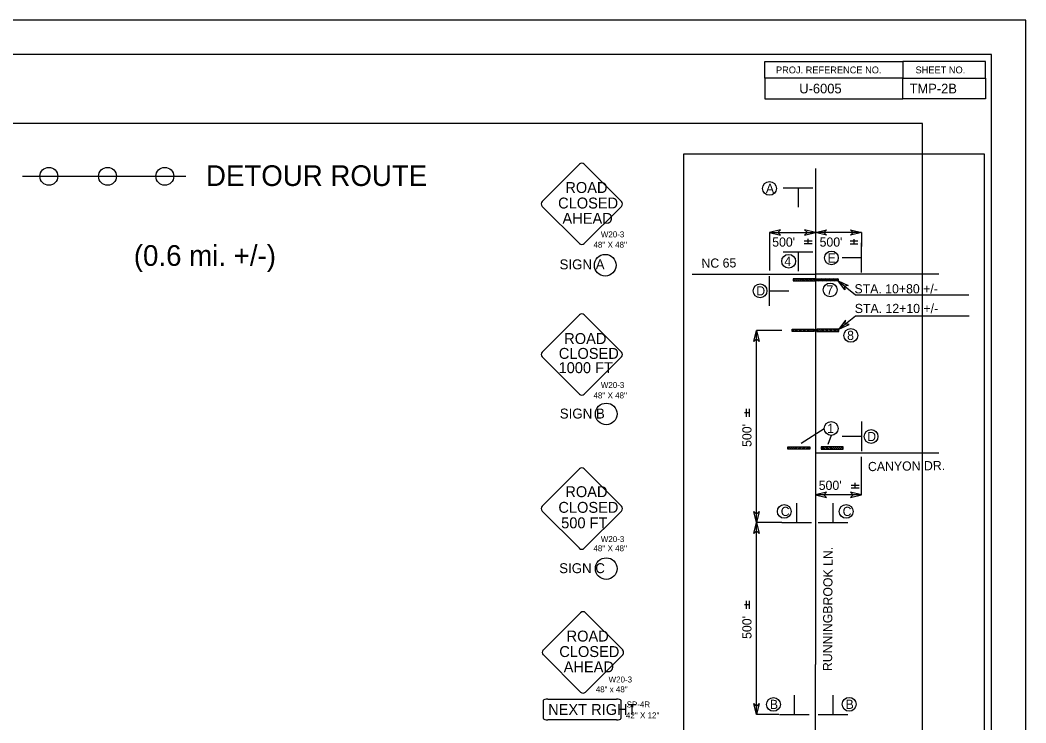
# Model space of a CAD drawing. Extents: x 1615234 to 1620694, y 898143 to 902846.
# Drawn here: x 1618110 to 1620298, y 901317 to 902846 of the extents above; entities that cross this region are included whole.
import ezdxf

# ---------------------------------------------------------------- set-up
doc = ezdxf.new("R2010")
doc.units = 0
for name, color, linetype in [('DEV BORDER CELL', 7, 'Continuous'), ('Old_Level_28', 7, 'Continuous'), ('Old_Level_8', 7, 'Continuous'), ('Scratch_Level_0', 7, 'Continuous'), ('Sheet Plot Border Outside CELL', 7, 'Continuous'), ('WZ INSETA CELL', 7, 'Continuous')]:
    doc.layers.add(name, color=color, linetype=linetype)

msp = doc.modelspace()

# ---------------------------------------------------------------- linework, layer by layer
at = {"layer": 'DEV BORDER CELL'}
msp.add_line((1620030, 902719.8), (1620210, 902719.8), dxfattribs=at)
for points in [[(1620223.1, 902771.2), (1615723.1, 902771.2), (1615723.1, 899621.2), (1620223.1, 899621.2)], [(1619730, 902755.8), (1620030, 902755.8), (1620030, 902719.8), (1619730, 902719.8)], [(1620030, 902719.8), (1620210, 902719.8), (1620210, 902755.8), (1620030, 902755.8)], [(1620030, 902719.8), (1619730, 902719.8), (1619730, 902674.8), (1620030, 902674.8)], [(1620030, 902719.8), (1620210, 902719.8), (1620210, 902674.8), (1620030, 902674.8)]]:
    msp.add_lwpolyline(points, close=True, dxfattribs=at)
at = {"layer": 'Old_Level_28'}
for p, q in [((1618114.5, 902506.3), (1618470.3, 902506.3)), ((1619418, 902441), (1619337.1, 902360)), ((1619418, 901777.9), (1619337.1, 901697)), ((1619258.2, 901368.9), (1619407, 901368.9))]:
    msp.add_line(p, q, dxfattribs=at)
for points in [[(1619245.4, 902451.7), (1619326.4, 902532.6)], [(1619337.1, 902532.6), (1619418, 902451.7)], [(1619326.4, 902360), (1619245.4, 902441)], [(1619245.4, 902123.9), (1619326.4, 902204.8)], [(1619337.1, 902204.8), (1619418, 902123.9)], [(1619326.4, 902032.3), (1619245.4, 902113.2)], [(1619418, 902113.2), (1619337.1, 902032.3)], [(1619245.4, 901788.6), (1619326.4, 901869.5)], [(1619337.1, 901869.5), (1619418, 901788.6)], [(1619326.4, 901697), (1619245.4, 901777.9)], [(1619248.1, 901475.7), (1619329.1, 901556.6)], [(1619339.7, 901556.6), (1619420.7, 901475.7)], [(1619329.1, 901384), (1619248.1, 901465)], [(1619420.7, 901465), (1619339.7, 901384)], [(1619248.3, 901326.2), (1619248.3, 901366.2)], [(1619416.8, 901366.2), (1619416.8, 901326.2)], [(1619407, 901323.5), (1619258.2, 901323.5)]]:
    msp.add_lwpolyline(points, dxfattribs=at)
for centre in [(1619382.7, 902312.8), (1619385, 901989.2), (1619385, 901652.6)]:
    msp.add_circle(centre, 23.6, dxfattribs=at)
for centre, start, end in [((1619331.7, 902527.3), 44.987, 135), ((1619250.8, 902446.3), 135, 225), ((1619412.7, 902446.3), 315, 45), ((1619331.7, 902365.4), 225, 315), ((1619331.7, 902199.5), 44.987, 135), ((1619250.8, 902118.6), 135, 225), ((1619412.7, 902118.6), 315, 45), ((1619331.7, 902037.6), 225, 315), ((1619331.7, 901864.2), 44.987, 135), ((1619250.8, 901783.2), 135, 225), ((1619412.7, 901783.2), 315, 45), ((1619331.7, 901702.3), 225, 315), ((1619334.4, 901551.3), 44.987, 135), ((1619253.4, 901470.3), 135, 225), ((1619415.3, 901470.3), 315, 45), ((1619334.4, 901389.4), 225, 315)]:
    msp.add_arc(centre, 7.56, start, end, dxfattribs=at)
for centre, major_axis, start_param, end_param in [((1619258.2, 901366.2), (-9.83, 0), 4.712162, 6.283185), ((1619407, 901366.2), (9.83, 0), 0, 1.570796), ((1619258.2, 901326.2), (-9.83, 0), 0, 1.570796), ((1619407, 901326.2), (-9.83, 0), 1.570796, 3.141593)]:
    msp.add_ellipse(centre, major_axis=major_axis, ratio=0.269231, start_param=start_param, end_param=end_param, dxfattribs=at)
at = {"layer": 'Old_Level_8'}
for centre in [(1618172.1, 902506.3), (1618299.8, 902506.3), (1618424.4, 902506.3)]:
    msp.add_circle(centre, 19.5, dxfattribs=at)
at = {"layer": 'Scratch_Level_0'}
msp.add_lwpolyline([(1620073.1, 902621.2), (1615873.1, 902621.2), (1615873.1, 899771.2), (1618509.6, 899771.2), (1618509.6, 900126), (1620073.1, 900126)], close=True, dxfattribs=at)
at = {"layer": 'Sheet Plot Border Outside CELL'}
msp.add_lwpolyline([(1615234.1, 899546.2), (1620298.1, 899546.2), (1620298.1, 902846.2), (1615234.1, 902846.2)], close=True, dxfattribs=at)
at = {"layer": 'WZ INSETA CELL'}
for p, q in [((1619840.4, 902523.5), (1619840.4, 902393.2)), ((1619769.9, 902481.4), (1619834.7, 902481.4)), ((1619802.6, 902481.4), (1619802.6, 902439.4)), ((1619764.3, 902390.1), (1619740.4, 902384.2)), ((1619758.3, 902384.2), (1619764.3, 902390.1)), ((1619840.4, 902384.2), (1619816.6, 902390.1)), ((1619816.6, 902390.1), (1619822.6, 902384.2)), ((1619840.4, 902393.2), (1619840.4, 902293.4)), ((1619840.4, 902384.2), (1619864.3, 902390.1)), ((1619864.3, 902390.1), (1619858.3, 902384.2)), ((1619916.6, 902390.1), (1619940.4, 902384.2)), ((1619922.6, 902384.2), (1619916.6, 902390.1)), ((1619740.4, 902384.2), (1619840.4, 902384.2)), ((1619740.4, 902384.2), (1619764.3, 902378.2)), ((1619740.4, 902384.2), (1619740.4, 902301.5)), ((1619764.3, 902378.2), (1619758.3, 902384.2)), ((1619832.8, 902365.5), (1619815.5, 902365.5)), ((1619816.6, 902378.2), (1619840.4, 902384.2)), ((1619822.6, 902384.2), (1619816.6, 902378.2)), ((1619824.1, 902365.5), (1619824.1, 902370.1)), ((1619824.1, 902360.9), (1619824.1, 902365.5)), ((1619940.4, 902384.2), (1619840.4, 902384.2)), ((1619864.3, 902378.2), (1619840.4, 902384.2)), ((1619858.3, 902384.2), (1619864.3, 902378.2)), ((1619932.7, 902365.1), (1619915.4, 902365.1)), ((1619940.4, 902384.2), (1619916.6, 902378.2)), ((1619916.6, 902378.2), (1619922.6, 902384.2)), ((1619924.1, 902365.1), (1619924.1, 902369.7)), ((1619924.1, 902360.5), (1619924.1, 902365.1)), ((1619940.4, 902384.2), (1619940.4, 902353.7)), ((1619769.9, 902342.1), (1619834.7, 902342.1)), ((1619802.6, 902342.1), (1619802.6, 902300.1)), ((1619832.8, 902359.5), (1619815.5, 902359.5)), ((1619932.7, 902359), (1619915.4, 902359)), ((1619940.4, 902296.7), (1619940.4, 902361.5)), ((1619940.4, 902329.3), (1619898.5, 902329.3)), ((1619572.2, 902293.4), (1619723.2, 902293.4)), ((1619723.2, 902293.4), (1619840.4, 902293.4)), ((1619740.4, 902224.3), (1619740.4, 902289.1)), ((1619791.4, 902283.4), (1619791.4, 902278.6)), ((1619796.2, 902278.6), (1619791.4, 902283.4)), ((1619791.4, 902278.6), (1619796.2, 902278.6)), ((1619795.7, 902283.4), (1619800.5, 902278.6)), ((1619800.1, 902283.4), (1619795.7, 902283.4)), ((1619804.8, 902278.6), (1619800.1, 902283.4)), ((1619800.5, 902278.6), (1619804.8, 902278.6)), ((1619804.4, 902283.4), (1619809.1, 902278.6)), ((1619808.7, 902283.4), (1619804.4, 902283.4)), ((1619813.4, 902278.6), (1619808.7, 902283.4)), ((1619809.1, 902278.6), (1619813.4, 902278.6)), ((1619813, 902283.4), (1619817.7, 902278.6)), ((1619817.3, 902283.4), (1619813, 902283.4)), ((1619822, 902278.6), (1619817.3, 902283.4)), ((1619817.7, 902278.6), (1619822, 902278.6)), ((1619821.6, 902283.4), (1619826.4, 902278.6)), ((1619825.9, 902283.4), (1619821.6, 902283.4)), ((1619830.7, 902278.6), (1619825.9, 902283.4)), ((1619826.4, 902278.6), (1619830.7, 902278.6)), ((1619830.2, 902283.4), (1619835, 902278.6)), ((1619834.5, 902283.4), (1619830.2, 902283.4)), ((1619839.3, 902278.6), (1619834.5, 902283.4)), ((1619835, 902278.6), (1619839.3, 902278.6)), ((1620108.7, 902293.4), (1619840.4, 902293.4)), ((1619840.4, 902293.4), (1619840.4, 902104.6)), ((1619840.4, 902293.4), (1619840.4, 902104.6)), ((1619841.4, 902278.6), (1619841.4, 902283.4)), ((1619841.4, 902283.4), (1619846.1, 902283.4)), ((1619846.1, 902283.4), (1619841.4, 902278.6)), ((1619845.7, 902278.6), (1619850.5, 902283.4)), ((1619850, 902278.6), (1619845.7, 902278.6)), ((1619854.8, 902283.4), (1619850, 902278.6)), ((1619850.5, 902283.4), (1619854.8, 902283.4)), ((1619854.4, 902278.6), (1619859.1, 902283.4)), ((1619858.7, 902278.6), (1619854.4, 902278.6)), ((1619863.4, 902283.4), (1619858.7, 902278.6)), ((1619859.1, 902283.4), (1619863.4, 902283.4)), ((1619863, 902278.6), (1619867.7, 902283.4)), ((1619867.3, 902278.6), (1619863, 902278.6)), ((1619872, 902283.4), (1619867.3, 902278.6)), ((1619867.7, 902283.4), (1619872, 902283.4)), ((1619871.6, 902278.6), (1619876.4, 902283.4)), ((1619875.9, 902278.6), (1619871.6, 902278.6)), ((1619880.7, 902283.4), (1619875.9, 902278.6)), ((1619876.4, 902283.4), (1619880.7, 902283.4)), ((1619880.2, 902278.6), (1619885, 902283.4)), ((1619884.5, 902278.6), (1619880.2, 902278.6)), ((1619889.3, 902283.4), (1619884.5, 902278.6)), ((1619885, 902283.4), (1619889.3, 902283.4)), ((1619889.3, 902278.7), (1619927, 902248.3)), ((1619904.1, 902259.1), (1619889.3, 902278.7)), ((1619889.3, 902278.7), (1619911.6, 902268.4)), ((1619740.4, 902256.9), (1619782.4, 902256.9)), ((1619911.6, 902268.4), (1619903.2, 902267.5)), ((1619903.2, 902267.5), (1619904.1, 902259.1)), ((1619927, 902248.3), (1620174.2, 902248.3)), ((1619891.1, 902173.4), (1619927.5, 902202.9)), ((1619905.8, 902193), (1619891.1, 902173.4)), ((1619904.9, 902184.6), (1619905.8, 902193)), ((1619927.5, 902202.9), (1620174.7, 902202.9)), ((1619705.9, 902147), (1619711.9, 902170.8)), ((1619766.7, 902170.8), (1619711.9, 902170.8)), ((1619711.9, 901753), (1619711.9, 902170.8)), ((1619711.9, 902170.8), (1619717.8, 902147)), ((1619789.5, 902168.6), (1619794.3, 902173.4)), ((1619793.8, 902168.6), (1619789.5, 902168.6)), ((1619798.6, 902173.4), (1619793.8, 902168.6)), ((1619794.3, 902173.4), (1619798.6, 902173.4)), ((1619798.1, 902168.6), (1619802.9, 902173.4)), ((1619802.4, 902168.6), (1619798.1, 902168.6)), ((1619807.2, 902173.4), (1619802.4, 902168.6)), ((1619802.9, 902173.4), (1619807.2, 902173.4)), ((1619806.8, 902168.6), (1619811.5, 902173.4)), ((1619811.1, 902168.6), (1619806.8, 902168.6)), ((1619815.8, 902173.4), (1619811.1, 902168.6)), ((1619811.5, 902173.4), (1619815.8, 902173.4)), ((1619815.4, 902168.6), (1619820.1, 902173.4)), ((1619819.7, 902168.6), (1619815.4, 902168.6)), ((1619824.4, 902173.4), (1619819.7, 902168.6)), ((1619820.1, 902173.4), (1619824.4, 902173.4)), ((1619824, 902168.6), (1619828.7, 902173.4)), ((1619828.3, 902168.6), (1619824, 902168.6)), ((1619833, 902173.4), (1619828.3, 902168.6)), ((1619828.7, 902173.4), (1619833, 902173.4)), ((1619832.6, 902168.6), (1619837.3, 902173.4)), ((1619837.3, 902168.6), (1619832.6, 902168.6)), ((1619837.3, 902173.4), (1619837.3, 902168.6)), ((1619847.5, 902173.4), (1619843.2, 902173.4)), ((1619843.2, 902173.4), (1619848, 902168.6)), ((1619852.3, 902168.6), (1619847.5, 902173.4)), ((1619848, 902168.6), (1619852.3, 902168.6)), ((1619856.1, 902173.4), (1619851.8, 902173.4)), ((1619851.8, 902173.4), (1619856.6, 902168.6)), ((1619860.9, 902168.6), (1619856.1, 902173.4)), ((1619856.6, 902168.6), (1619860.9, 902168.6)), ((1619864.8, 902173.4), (1619860.5, 902173.4)), ((1619860.5, 902173.4), (1619865.2, 902168.6)), ((1619869.5, 902168.6), (1619864.8, 902173.4)), ((1619865.2, 902168.6), (1619869.5, 902168.6)), ((1619873.4, 902173.4), (1619869.1, 902173.4)), ((1619869.1, 902173.4), (1619873.8, 902168.6)), ((1619878.1, 902168.6), (1619873.4, 902173.4)), ((1619873.8, 902168.6), (1619878.1, 902168.6)), ((1619882, 902173.4), (1619877.7, 902173.4)), ((1619877.7, 902173.4), (1619882.4, 902168.6)), ((1619886.7, 902168.6), (1619882, 902173.4)), ((1619882.4, 902168.6), (1619886.7, 902168.6)), ((1619891.1, 902173.4), (1619886.3, 902173.4)), ((1619886.3, 902173.4), (1619891.1, 902168.6)), ((1619891.1, 902173.4), (1619913.3, 902183.7)), ((1619891.1, 902168.6), (1619891.1, 902173.4)), ((1619913.3, 902183.7), (1619904.9, 902184.6)), ((1619711.9, 902153), (1619705.9, 902147)), ((1619717.8, 902147), (1619711.9, 902153)), ((1619840.4, 902104.6), (1619840.4, 902015.2)), ((1619840.4, 902015.2), (1619840.4, 901715)), ((1619690.5, 901991.5), (1619685.9, 901991.5)), ((1619690.5, 901982.9), (1619690.5, 902000.2)), ((1619695.1, 901991.5), (1619690.5, 901991.5)), ((1619696.5, 901982.9), (1619696.5, 902000.2)), ((1619940.4, 901972.9), (1619940.4, 901908.1)), ((1619809.2, 901925.5), (1619859.3, 901957.7)), ((1619874.3, 901942.7), (1619867.1, 901923.1)), ((1619940.4, 901940.3), (1619898.5, 901940.3)), ((1619780.2, 901912.7), (1619785, 901917.5)), ((1619784.5, 901912.7), (1619780.2, 901912.7)), ((1619789.3, 901917.5), (1619784.5, 901912.7)), ((1619785, 901917.5), (1619789.3, 901917.5)), ((1619788.8, 901912.7), (1619793.6, 901917.5)), ((1619793.1, 901912.7), (1619788.8, 901912.7)), ((1619797.9, 901917.5), (1619793.1, 901912.7)), ((1619793.6, 901917.5), (1619797.9, 901917.5)), ((1619797.5, 901912.7), (1619802.2, 901917.5)), ((1619801.8, 901912.7), (1619797.5, 901912.7)), ((1619806.6, 901917.5), (1619801.8, 901912.7)), ((1619802.2, 901917.5), (1619806.6, 901917.5)), ((1619806.2, 901912.7), (1619810.9, 901917.5)), ((1619810.5, 901912.7), (1619806.2, 901912.7)), ((1619815.2, 901917.5), (1619810.5, 901912.7)), ((1619810.9, 901917.5), (1619815.2, 901917.5)), ((1619814.8, 901912.7), (1619819.5, 901917.5)), ((1619819.1, 901912.7), (1619814.8, 901912.7)), ((1619823.8, 901917.5), (1619819.1, 901912.7)), ((1619819.5, 901917.5), (1619823.8, 901917.5)), ((1619823.4, 901912.7), (1619828.1, 901917.5)), ((1619828.1, 901912.7), (1619823.4, 901912.7)), ((1619828.1, 901917.5), (1619828.1, 901912.7)), ((1619856.7, 901917.4), (1619852.4, 901917.4)), ((1619852.4, 901917.4), (1619857.2, 901912.6)), ((1619861.5, 901912.6), (1619856.7, 901917.4)), ((1619857.2, 901912.6), (1619861.5, 901912.6)), ((1619865.3, 901917.4), (1619861, 901917.4)), ((1619861, 901917.4), (1619865.8, 901912.6)), ((1619870.1, 901912.6), (1619865.3, 901917.4)), ((1619865.8, 901912.6), (1619870.1, 901912.6)), ((1619874, 901917.4), (1619869.7, 901917.4)), ((1619869.7, 901917.4), (1619874.4, 901912.6)), ((1619878.8, 901912.6), (1619874, 901917.4)), ((1619874.4, 901912.6), (1619878.8, 901912.6)), ((1619882.7, 901917.4), (1619878.3, 901917.4)), ((1619878.3, 901917.4), (1619883.1, 901912.6)), ((1619887.4, 901912.6), (1619882.7, 901917.4)), ((1619883.1, 901912.6), (1619887.4, 901912.6)), ((1619891.3, 901917.4), (1619887, 901917.4)), ((1619887, 901917.4), (1619891.7, 901912.6)), ((1619896, 901912.6), (1619891.3, 901917.4)), ((1619891.7, 901912.6), (1619896, 901912.6)), ((1619900.3, 901917.4), (1619895.6, 901917.4)), ((1619895.6, 901917.4), (1619900.3, 901912.6)), ((1619900.3, 901912.6), (1619900.3, 901917.4)), ((1620108.7, 901903.8), (1619840.4, 901903.8)), ((1619940.4, 901813), (1619940.4, 901895.8)), ((1619926.5, 901834.4), (1619926.5, 901839)), ((1619864.3, 901819), (1619840.4, 901813)), ((1619858.3, 901813), (1619864.3, 901819)), ((1619940.4, 901813), (1619916.6, 901819)), ((1619916.6, 901819), (1619922.6, 901813)), ((1619917.8, 901834.4), (1619935.1, 901834.4)), ((1619917.8, 901828.4), (1619935.1, 901828.4)), ((1619926.5, 901829.8), (1619926.5, 901834.4)), ((1619799.4, 901753), (1619799.4, 901795)), ((1619940.4, 901813), (1619840.4, 901813)), ((1619840.4, 901813), (1619864.3, 901807.1)), ((1619864.3, 901807.1), (1619858.3, 901813)), ((1619878.8, 901753), (1619878.8, 901795)), ((1619916.6, 901807.1), (1619940.4, 901813)), ((1619922.6, 901813), (1619916.6, 901807.1)), ((1619711.9, 901753), (1619705.9, 901776.8)), ((1619705.9, 901776.8), (1619711.9, 901770.8)), ((1619717.8, 901776.8), (1619711.9, 901753)), ((1619711.9, 901770.8), (1619717.8, 901776.8)), ((1619705.9, 901729.2), (1619711.9, 901753)), ((1619711.9, 901335.1), (1619711.9, 901753)), ((1619711.9, 901753), (1619717.8, 901729.2)), ((1619766.7, 901753), (1619711.9, 901753)), ((1619766.7, 901753), (1619831.5, 901753)), ((1619846.2, 901753), (1619911, 901753)), ((1619711.9, 901735.1), (1619705.9, 901729.2)), ((1619717.8, 901729.2), (1619711.9, 901735.1)), ((1619840.4, 901715), (1619840.4, 901615)), ((1619840.4, 901615), (1619840.4, 901443.8)), ((1619690.5, 901565), (1619690.5, 901582.3)), ((1619696.5, 901565), (1619696.5, 901582.3)), ((1619690.5, 901573.6), (1619685.9, 901573.6)), ((1619695.1, 901573.6), (1619690.5, 901573.6)), ((1619840.4, 901274.7), (1619840.4, 901443.8)), ((1619711.9, 901335.1), (1619705.9, 901358.9)), ((1619705.9, 901358.9), (1619711.9, 901353)), ((1619717.8, 901358.9), (1619711.9, 901335.1)), ((1619711.9, 901353), (1619717.8, 901358.9)), ((1619794.3, 901335.1), (1619794.3, 901377.1)), ((1619878.8, 901335.1), (1619878.8, 901377.1)), ((1619760.3, 901335.1), (1619711.9, 901335.1)), ((1619761.6, 901335.1), (1619826.4, 901335.1)), ((1619846.2, 901335.1), (1619911, 901335.1))]:
    msp.add_line(p, q, dxfattribs=at)
for points in [[(1620207.6, 900319.6), (1619553.5, 900319.6), (1619553.5, 902555.4), (1620207.6, 902555.4)], [(1619791.4, 902278.6), (1619839.3, 902278.6), (1619839.3, 902283.3), (1619791.4, 902283.3)], [(1619841.4, 902283.4), (1619889.3, 902283.4), (1619889.3, 902278.7), (1619841.4, 902278.7)], [(1619837.3, 902168.6), (1619789.5, 902168.6), (1619789.5, 902173.4), (1619837.3, 902173.4)], [(1619891.1, 902173.4), (1619843.2, 902173.4), (1619843.2, 902168.7), (1619891.1, 902168.7)], [(1619828.1, 901912.7), (1619780.2, 901912.7), (1619780.2, 901917.4), (1619828.1, 901917.4)], [(1619900.3, 901917.4), (1619852.4, 901917.4), (1619852.4, 901912.7), (1619900.3, 901912.7)]]:
    msp.add_lwpolyline(points, close=True, dxfattribs=at)
for centre in [(1619740.2, 902480), (1619874.9, 902328.7), (1619781.9, 902321.5), (1619719.7, 902257.1), (1619872.2, 902259), (1619917.1, 902160.2), (1619874.3, 901957.7), (1619961.2, 901940.1), (1619772.4, 901777.2), (1619907.1, 901777.2), (1619748.8, 901357.2), (1619913.5, 901357.4)]:
    msp.add_circle(centre, 15, dxfattribs=at)

# ---------------------------------------------------------------- texts
at = {"layer": 'DEV BORDER CELL'}
for s, height, p in [('PROJ. REFERENCE NO.', 14.998, (1619754.3, 902730.3)), ('SHEET NO.', 15, (1620058, 902730.3))]:
    msp.add_text(s, height=height, rotation=0.0006, dxfattribs=at).set_placement(p)
for s, p in [('U-6005', (1619805, 902686.8)), ('TMP-2B', (1620045, 902686.8))]:
    msp.add_text(s, height=21, dxfattribs=at).set_placement(p)
at = {"layer": 'Old_Level_28'}
for s, height, p in [('ROAD', 23.76, (1619295.9, 902470.1)), ('CLOSED', 23.76, (1619280.2, 902436.3)), ('AHEAD', 23.76, (1619289.7, 902403)), ('W20-3', 12.96, (1619373.2, 902373.5)), ("48'' X 48''", 12.96, (1619357.2, 902350.9)), ('ROAD', 23.76, (1619298.6, 901494)), ('CLOSED', 23.76, (1619282.8, 901460.3)), ('AHEAD', 23.76, (1619292.3, 901427)), ('W20-3', 12.96, (1619390.1, 901404.9))]:
    msp.add_text(s, height=height, rotation=360, dxfattribs=at).set_placement(p)
for s, height, p in [('SIGN A', 21.6, (1619283.4, 902303.9)), ('ROAD', 23.76, (1619293.5, 902141.4)), ('CLOSED', 23.76, (1619281.7, 902109.1)), ('1000 FT', 23.76, (1619281.2, 902078)), ('W20-3', 12.96, (1619373.2, 902045.7)), ("48'' X 48''", 12.96, (1619357.2, 902023.1)), ('SIGN B', 21.6, (1619283.9, 901979.3)), ('ROAD', 23.76, (1619295.9, 901808.2)), ('CLOSED', 23.76, (1619280.8, 901774.1)), ('500 FT', 23.76, (1619286.9, 901740.4)), ('W20-3', 12.96, (1619373.2, 901710.4)), ("48'' X 48''", 12.96, (1619357.2, 901690.4)), ('SIGN C', 21.6, (1619282.6, 901642.8)), ('48" x 48"', 12.96, (1619362.2, 901383.5)), ('NEXT RIGHT', 23.76, (1619258.5, 901334.3)), ('SP-4R', 12.96, (1619429.4, 901350.6)), ("42'' X 12''", 12.96, (1619427.8, 901326.9))]:
    msp.add_text(s, height=height, dxfattribs=at).set_placement(p)
at = {"layer": 'Old_Level_8'}
for s, p in [('DETOUR ROUTE', (1618514, 902485.3)), ('(0.6 mi. +/-)', (1618357, 902311.5))]:
    msp.add_text(s, height=45, rotation=360, dxfattribs=at).set_placement(p)
at = {"layer": 'WZ INSETA CELL'}
for s, p in [('A', (1619732.3, 902470)), ("500'", (1619746.1, 902353.3)), ("500'", (1619849.2, 902353.3)), ('4', (1619772.5, 902311.5)), ('E', (1619866.6, 902318.7)), ('D', (1619711.4, 902247.1)), ('7', (1619864.1, 902249)), ('STA. 10+80 +/-', (1619925.1, 902251.6)), ('STA. 12+10 +/-', (1619925.7, 902208.8)), ('8', (1619909.1, 902150.2)), ('1', (1619865.7, 901947.8)), ('D', (1619952.8, 901930.1)), ("500'", (1619847.3, 901823.9)), ('C', (1619764.7, 901767.2)), ('C', (1619899.3, 901767.2)), ('B', (1619740.9, 901347.2)), ('B', (1619905.7, 901347.4))]:
    msp.add_text(s, height=20, dxfattribs=at).set_placement(p)
for s, rotation, p in [('NC 65', 0.8536, (1619592.3, 902307)), ("500'", 90, (1619701, 901917.5)), ('CANYON DR.', 0.8536, (1619954.6, 901864.7)), ('RUNNINGBROOK LN.', 89.7306, (1619876.3, 901429.7)), ("500'", 90, (1619701, 901499.7))]:
    msp.add_text(s, height=20, rotation=rotation, dxfattribs=at).set_placement(p)

doc.saveas('drawing.dxf')
